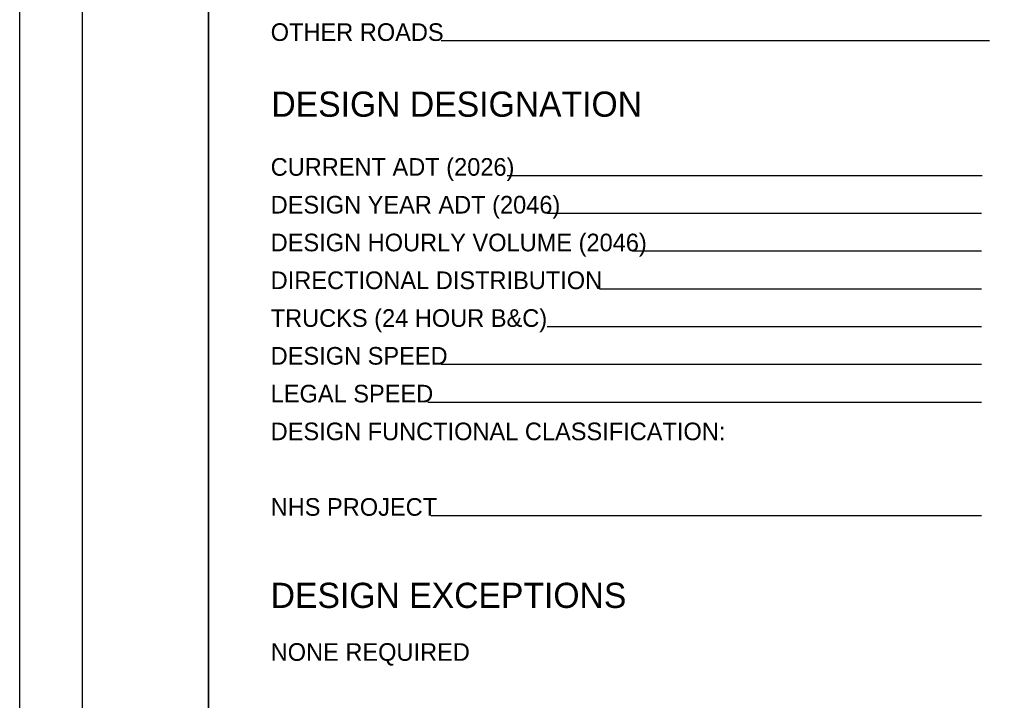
# Model space of a CAD drawing. Extents: x 0 to 34, y 0 to 22.
# Drawn here: x 0 to 7.72, y 5.64 to 11.05 of the extents above; entities that cross this region are included whole.
import ezdxf

# ---------------------------------------------------------------- set-up
doc = ezdxf.new("R2010")
doc.units = 0
for name, color, linetype in [('SH_Border', 7, 'Continuous'), ('SH_Cut_Line', 7, 'Continuous'), ('SH_Data', 7, 'Continuous'), ('SH_Text', 7, 'Continuous')]:
    doc.layers.add(name, color=color, linetype=linetype)

msp = doc.modelspace()

# ---------------------------------------------------------------- linework, layer by layer
at = {"layer": 'SH_Border'}
for points in [[(0.5, 21.5), (1.5, 21.5), (1.5, 0.5), (0.5, 0.5)], [(1.5, 21.5), (33.5, 21.5), (33.5, 0.5), (1.5, 0.5)]]:
    msp.add_lwpolyline(points, close=True, dxfattribs=at)
at = {"layer": 'SH_Cut_Line'}
msp.add_lwpolyline([(0, 0), (34, 0), (34, 22), (0, 22)], close=True, dxfattribs=at)
at = {"layer": 'SH_Data'}
for p, q in [((7.7, 10.8767), (3.3471, 10.8767)), ((7.6424, 9.8062), (3.871, 9.8062)), ((7.6368, 9.5062), (4.1885, 9.5062)), ((7.6368, 9.2062), (4.8723, 9.2062)), ((7.6368, 8.9062), (4.6037, 8.9062)), ((7.6368, 8.6062), (4.1885, 8.6062)), ((7.6368, 8.3062), (3.346, 8.3062)), ((7.6368, 8.0062), (3.2422, 8.0062)), ((7.6368, 7.1062), (3.2669, 7.1062))]:
    msp.add_line(p, q, dxfattribs=at)

# ---------------------------------------------------------------- texts
msp.add_text('DESIGN DESIGNATION', height=0.2, dxfattribs=at).set_placement((2, 10.2747))
at = {"layer": 'SH_Text'}
for s, height, p in [('OTHER ROADS', 0.14, (1.9944, 10.8767)), ('CURRENT ADT (2026)', 0.14, (1.9944, 9.8062)), ('DESIGN YEAR ADT (2046)', 0.14, (1.9944, 9.5062)), ('DESIGN HOURLY VOLUME (2046)', 0.14, (1.9944, 9.2062)), ('DIRECTIONAL DISTRIBUTION', 0.14, (1.9944, 8.9062)), ('TRUCKS (24 HOUR B&C)', 0.14, (1.9944, 8.6062)), ('DESIGN SPEED', 0.14, (1.9944, 8.3062)), ('LEGAL SPEED', 0.14, (1.9944, 8.0062)), ('DESIGN FUNCTIONAL CLASSIFICATION:', 0.14, (1.9944, 7.7062)), ('NHS PROJECT', 0.14, (1.9944, 7.1062)), ('DESIGN EXCEPTIONS', 0.2, (1.9944, 6.3744)), ('NONE REQUIRED', 0.14, (1.9944, 5.9544))]:
    msp.add_text(s, height=height, dxfattribs=at).set_placement(p)

doc.saveas('drawing.dxf')
